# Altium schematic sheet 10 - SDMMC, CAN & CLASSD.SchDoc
size B; CompanyName: Microchip Technology Inc.; Organization: Microchip Technology; Address1: 2355 West Chandler Blvd.; Address2: Chandler, AZ  85224; Address4: USA; DocumentNumber: 10; SheetNumber: 10; SheetTotal: 13; SheetTitle: SDMMC, CAN & CLASSD
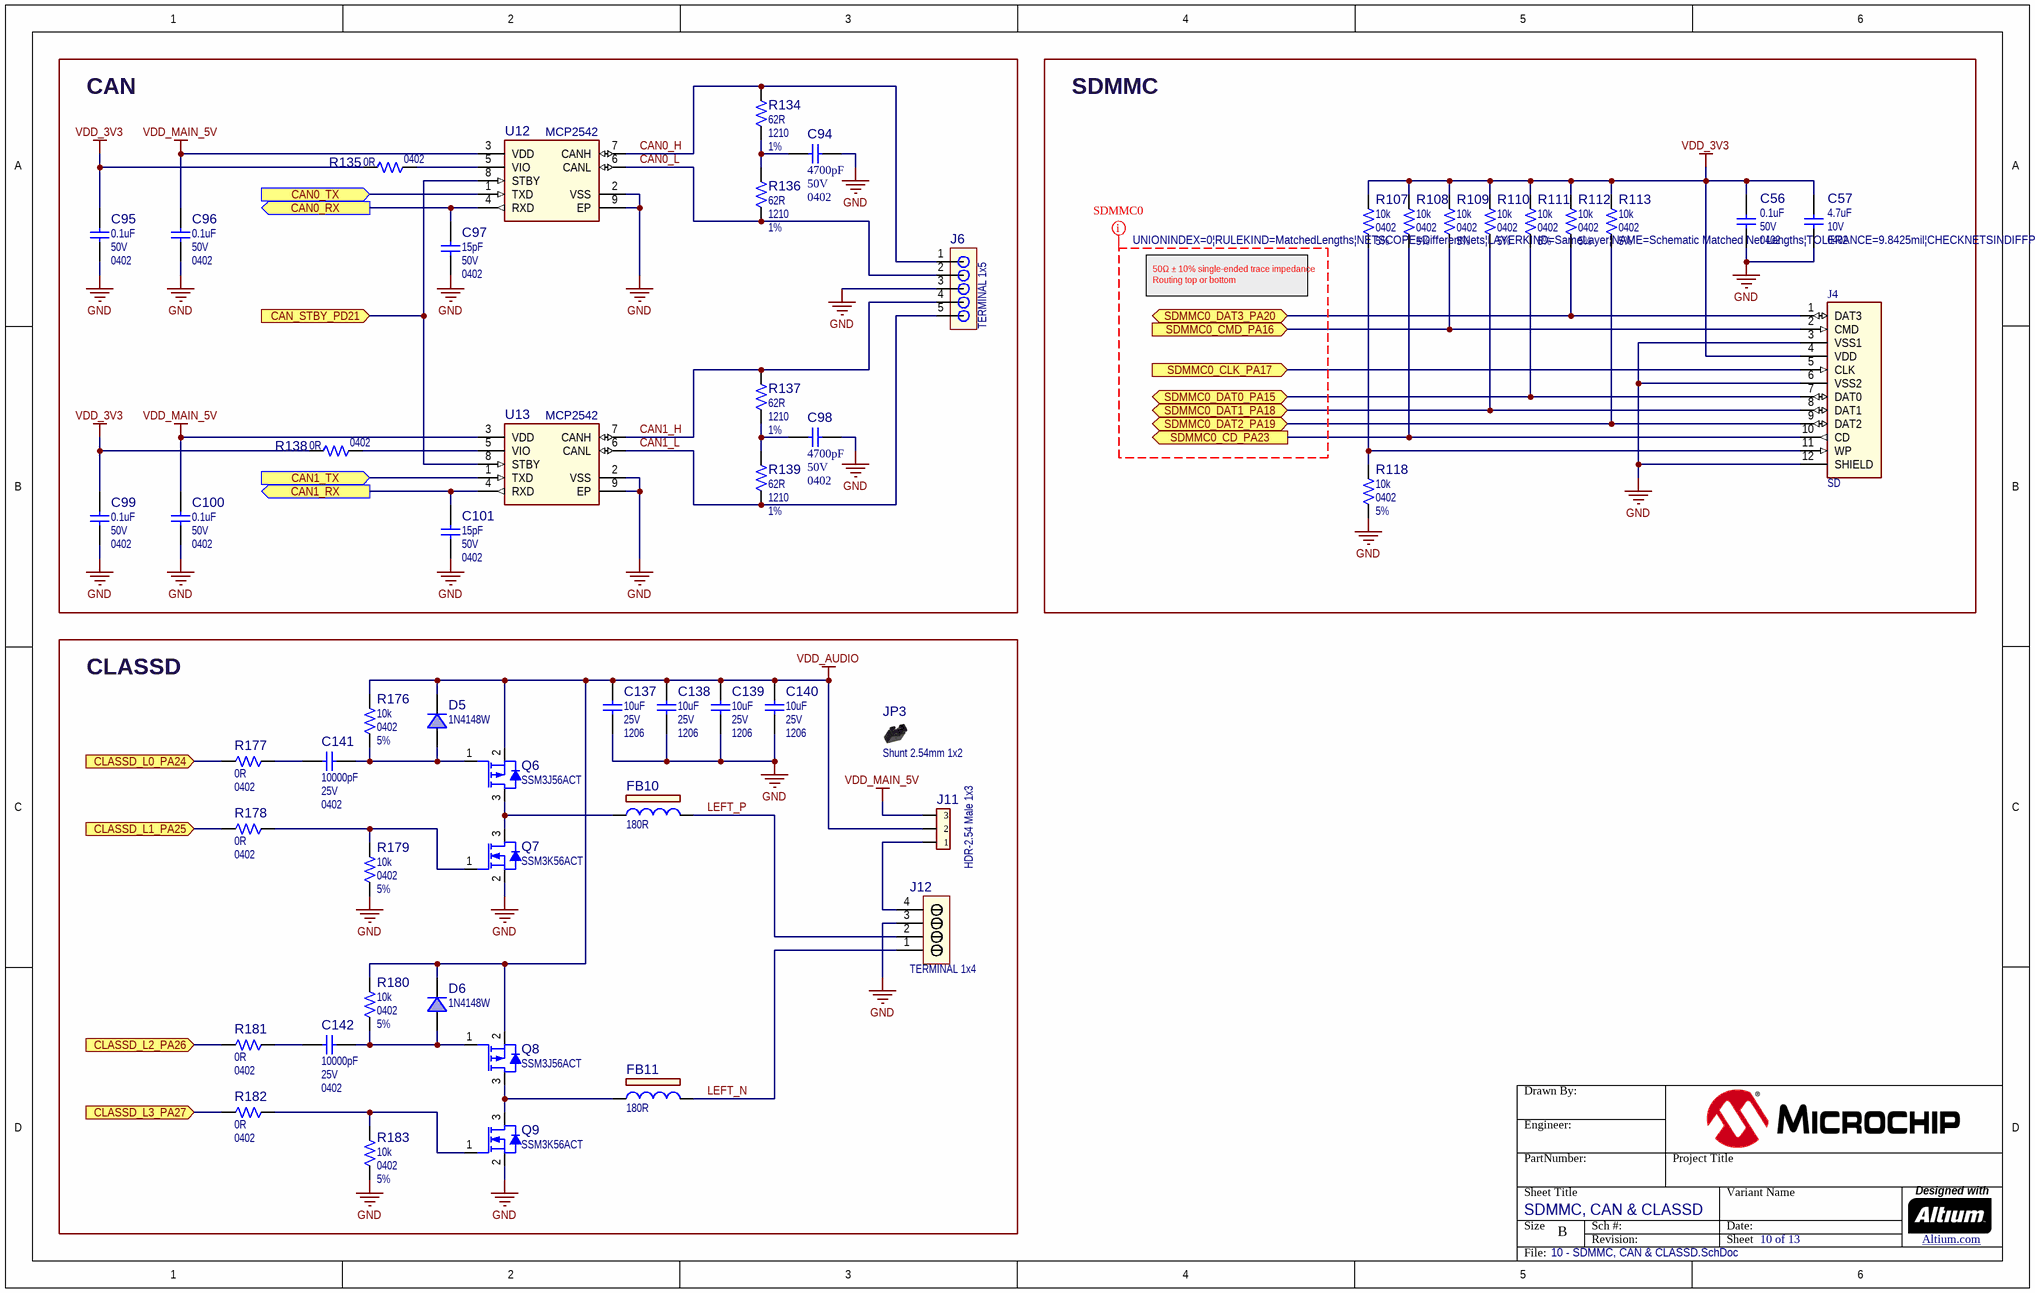
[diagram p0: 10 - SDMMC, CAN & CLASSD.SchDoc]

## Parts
?  (no value)  (graphical)
C56  value 0.1uF  Voltage: 50V  Package: 0402  [CAP_C_0402]  (hidden comment: Capacitor NP)
C57  value 4.7uF  Voltage: 10V  Package: 0402  [CAP_C_0402]  (hidden comment: Capacitor NP)
C94  value 4700pF  Voltage: 50V  Package: 0402  [CAP_C_0402]  (hidden comment: Capacitor NP)
C95  value 0.1uF  Voltage: 50V  Package: 0402  [CAP_C_0402]  (hidden comment: Capacitor NP)
C96  value 0.1uF  Voltage: 50V  Package: 0402  [CAP_C_0402]  (hidden comment: Capacitor NP)
C97  value 15pF  Voltage: 50V  Package: 0402  [CAP_C_0402]  (hidden comment: Capacitor NP)
C98  value 4700pF  Voltage: 50V  Package: 0402  [CAP_C_0402]  (hidden comment: Capacitor NP)
C99  value 0.1uF  Voltage: 50V  Package: 0402  [CAP_C_0402]  (hidden comment: Capacitor NP)
C100  value 0.1uF  Voltage: 50V  Package: 0402  [CAP_C_0402]  (hidden comment: Capacitor NP)
C101  value 15pF  Voltage: 50V  Package: 0402  [CAP_C_0402]  (hidden comment: Capacitor NP)
C137  value 10uF  Voltage: 25V  Package: 1206  [CAP_C_1206]  (hidden comment: Capacitor NP)
C138  value 10uF  Voltage: 25V  Package: 1206  [CAP_C_1206]  (hidden comment: Capacitor NP)
C139  value 10uF  Voltage: 25V  Package: 1206  [CAP_C_1206]  (hidden comment: Capacitor NP)
C140  value 10uF  Voltage: 25V  Package: 1206  [CAP_C_1206]  (hidden comment: Capacitor NP)
C141  value 10000pF  Voltage: 25V  Package: 0402  [CAP_C_0402]  (hidden comment: Capacitor NP)
C142  value 10000pF  Voltage: 25V  Package: 0402  [CAP_C_0402]  (hidden comment: Capacitor NP)
D5  value 1N4148W  [SOD-323]  (hidden comment: Diode Single)
D6  value 1N4148W  [SOD-323]  (hidden comment: Diode Single)
FB10  value 180R  [IND_C_0603]  (hidden comment: Ferrite Bead)
FB11  value 180R  [IND_C_0603]  (hidden comment: Ferrite Bead)
J4  value SD  [10067847-001RLF]  (hidden comment: CON SD CARD 11P_amphenol)
J6  value TERMINAL 1x5  [CON_TERMINAL_3.81_1x5_TH_RA_PHO_1727049]  (hidden comment: CON TERM BLK 1x5 TH Mount)
J11  value HDR-2.54 Male 1x3  [HDR_M_2.54_1x3]  (hidden comment: Header 1x3)
J12  value TERMINAL 1x4  [CON_TERMINAL_2.54_1x4_TH_RA_PHO_1725672]  (hidden comment: Header 1x4)
JP3  value Shunt 2.54mm 1x2  [Jumper_Mechanical]  (hidden comment: Jumper Mechanical)  (mechanical)
Q6  value SSM3J56ACT  [SOT-883]  (hidden comment: Transistor MOS-P GSD)
Q7  value SSM3K56ACT  [SOT-883]  (hidden comment: Transistor MOS-N GSD)
Q8  value SSM3J56ACT  [SOT-883]  (hidden comment: Transistor MOS-P GSD)
Q9  value SSM3K56ACT  [SOT-883]  (hidden comment: Transistor MOS-N GSD)
R107  value 10k  Package: 0402  Tolerance: 5%  [RES_C_0402]  (hidden comment: Resistor)
R108  value 10k  Package: 0402  Tolerance: 5%  [RES_C_0402]  (hidden comment: Resistor)
R109  value 10k  Package: 0402  Tolerance: 5%  [RES_C_0402]  (hidden comment: Resistor)
R110  value 10k  Package: 0402  Tolerance: 5%  [RES_C_0402]  (hidden comment: Resistor)
R111  value 10k  Package: 0402  Tolerance: 5%  [RES_C_0402]  (hidden comment: Resistor)
R112  value 10k  Package: 0402  Tolerance: 5%  [RES_C_0402]  (hidden comment: Resistor)
R113  value 10k  Package: 0402  Tolerance: 5%  [RES_C_0402]  (hidden comment: Resistor)
R118  value 10k  Package: 0402  Tolerance: 5%  [RES_C_0402]  (hidden comment: Resistor)
R134  value 62R  Package: 1210  Tolerance: 1%  [RES_C_1210]  (hidden comment: Resistor)
R135  value 0R  Package: 0402  [RES_C_0402]  (hidden comment: Resistor)
R136  value 62R  Package: 1210  Tolerance: 1%  [RES_C_1210]  (hidden comment: Resistor)
R137  value 62R  Package: 1210  Tolerance: 1%  [RES_C_1210]  (hidden comment: Resistor)
R138  value 0R  Package: 0402  [RES_C_0402]  (hidden comment: Resistor)
R139  value 62R  Package: 1210  Tolerance: 1%  [RES_C_1210]  (hidden comment: Resistor)
R176  value 10k  Package: 0402  Tolerance: 5%  [RES_C_0402]  (hidden comment: Resistor)
R177  value 0R  Package: 0402  [RES_C_0402]  (hidden comment: Resistor)
R178  value 0R  Package: 0402  [RES_C_0402]  (hidden comment: Resistor)
R179  value 10k  Package: 0402  Tolerance: 5%  [RES_C_0402]  (hidden comment: Resistor)
R180  value 10k  Package: 0402  Tolerance: 5%  [RES_C_0402]  (hidden comment: Resistor)
R181  value 0R  Package: 0402  [RES_C_0402]  (hidden comment: Resistor)
R182  value 0R  Package: 0402  [RES_C_0402]  (hidden comment: Resistor)
R183  value 10k  Package: 0402  Tolerance: 5%  [RES_C_0402]  (hidden comment: Resistor)
U12  value MCP2542  [DFN-8_3x3_EP2.4X1.55]  (hidden comment: MCP2542 DFN-8)
U13  value MCP2542  [DFN-8_3x3_EP2.4X1.55]  (hidden comment: MCP2542 DFN-8)

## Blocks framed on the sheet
CAN: C94-C101 J6 R134-R139 U12 U13
SDMMC: C56 C57 J4 R107-R113 R118
CLASSD: C137-C142 D5 D6 FB10 FB11 J11 J12 JP3 Q6-Q9 R176-R183

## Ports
CAN0_RX (out), CAN0_TX (in), CAN1_RX (out), CAN1_TX (in), CAN_STBY_PD21 (in), CLASSD_L0_PA24 (in), CLASSD_L1_PA25 (in), CLASSD_L2_PA26 (in), CLASSD_L3_PA27 (in), SDMMC0_CD_PA23 (out), SDMMC0_CLK_PA17 (in), SDMMC0_CMD_PA16 (in), SDMMC0_DAT0_PA15 (bidir), SDMMC0_DAT1_PA18 (bidir), SDMMC0_DAT2_PA19 (bidir), SDMMC0_DAT3_PA20 (bidir)

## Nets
GND: C56.2 C57.1 C94.1 C95.2 C96.2 C97.1 C98.1 C99.2 C100.2 C101.1 C137.1 C138.1 C139.1 C140.1 J4.3(VSS1) J4.6(VSS2) J4.12(SHIELD) J6.3 J12.3 Q7.2(S) Q9.2(S) R118.1 R179.1 R183.1 U12.2(VSS) U12.9(EP) U13.2(VSS) U13.9(EP)
VDD_3V3: C56.1 C57.2 C95.1 C99.1 J4.4(VDD) R107.2 R108.2 R109.2 R110.2 R111.2 R112.2 R113.2 R135.1 R138.1
VDD_AUDIO: C137.2 C138.2 C139.2 C140.2 D5.2(K) D6.2(K) J11.2 Q6.2(S) Q8.2(S) R176.2 R180.2
VDD_MAIN_5V: C96.1 C100.1 J11.3 U12.3(VDD) U13.3(VDD)
CAN0_H: J6.1 R134.2 U12.7(CANH)
CAN0_L: J6.2 R136.1 U12.6(CANL)
CAN0_RX: C97.2 U12.4(RXD) ; port CAN0_RX
CAN0_TX: U12.1(TXD) ; port CAN0_TX
CAN1_H: J6.4 R137.2 U13.7(CANH)
CAN1_L: J6.5 R139.1 U13.6(CANL)
CAN1_RX: C101.2 U13.4(RXD) ; port CAN1_RX
CAN1_TX: U13.1(TXD) ; port CAN1_TX
CAN_STBY_PD21: U12.8(STBY) U13.8(STBY) ; port CAN_STBY_PD21
CLASSD_L0_PA24: R177.1 ; port CLASSD_L0_PA24
CLASSD_L1_PA25: R178.1 ; port CLASSD_L1_PA25
CLASSD_L2_PA26: R181.1 ; port CLASSD_L2_PA26
CLASSD_L3_PA27: R182.1 ; port CLASSD_L3_PA27
LEFT_N: FB11.2 J12.1
LEFT_P: FB10.2 J12.2
SDMMC0_CD_PA23: J4.10(CD) R108.1 ; port SDMMC0_CD_PA23
SDMMC0_CLK_PA17: J4.5(CLK) ; port SDMMC0_CLK_PA17
SDMMC0_CMD_PA16: J4.2(CMD) R109.1 ; port SDMMC0_CMD_PA16
SDMMC0_DAT0_PA15: J4.7(DAT0) R111.1 ; port SDMMC0_DAT0_PA15
SDMMC0_DAT1_PA18: J4.8(DAT1) R110.1 ; port SDMMC0_DAT1_PA18
SDMMC0_DAT2_PA19: J4.9(DAT2) R113.1 ; port SDMMC0_DAT2_PA19
SDMMC0_DAT3_PA20: J4.1(DAT3) R112.1 ; port SDMMC0_DAT3_PA20
NetC94_2: C94.2 R134.1 R136.2
NetC98_2: C98.2 R137.1 R139.2
NetC141_1: C141.1 R177.2
NetC141_2: C141.2 D5.1(A) Q6.1(G) R176.1
NetC142_1: C142.1 R181.2
NetC142_2: C142.2 D6.1(A) Q8.1(G) R180.1
NetFB10_1: FB10.1 Q6.3(D) Q7.3(D)
NetFB11_1: FB11.1 Q8.3(D) Q9.3(D)
NetJ4_11: J4.11(WP) R107.1 R118.2
NetJ11_1: J11.1 J12.4
NetQ7_1: Q7.1(G) R178.2 R179.2
NetQ9_1: Q9.1(G) R182.2 R183.2
NetR135_2: R135.2 U12.5(VIO)
NetR138_2: R138.2 U13.5(VIO)

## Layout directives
net class SDMMC-0; rule Matched Net Lengths [Tolerance = 0.25mm]: (no net found under the mark)

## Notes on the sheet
- 50Ω ± 10% single-ended trace impedance
  Routing top or bottom

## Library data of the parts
? = Title Block B
C56 = CAP1463: Capacitor; Manufacturer 1: TDK Corporation; Manufacturer Part Number 1: C1005X7R1H104K050BB; Description_: CAP CER 0.1uF 50V 10% X7R SMD 0402; Dev Tools Status: Production; Tolerance: 10%; Temperature Coeffcient: X7R; Type: Ceramic; Populated: YES; Owner: Jamus Griego
C57 = CAP1684: Capacitor; Manufacturer 1: TDK Corporation; Manufacturer Part Number 1: C1005X5R1A475K050BC; Description_: CAP CER 4.7uF 10V 10% X5R SMD 0402; Dev Tools Status: Production; Tolerance: 10%; Temperature Coeffcient: X5R; Type: Ceramic; Owner: Jesus Aviles; Populated: YES
C94 C98 = CAP1391: Capacitor; Manufacturer 1: Murata Electronics North America; Manufacturer Part Number 1: GRM155R71H472KA01D; Description_: CAP CER 4700pF 50V 10% X7R SMD 0402 (Don't Use, Duplicate, use CAP1391); Dev Tools Status: Design; Tolerance: 10%; Temperature Coeffcient: X7R; Type: Ceramic; Owner: Gabor Bihari; Populated: YES
C95 C96 C99 C100 = CAP1463: Capacitor; Manufacturer 1: TDK Corporation; Manufacturer Part Number 1: C1005X7R1H104K050BB; Description_: CAP CER 0.1uF 50V 10% X7R SMD 0402; Dev Tools Status: Production; Tolerance: 10%; Temperature Coeffcient: X7R; Type: Ceramic; Owner: Jamus Griego; Populated: YES
C97 C101 = CAP0608: Capacitor; Manufacturer 1: Murata; Manufacturer Part Number 1: GRM1555C1H150JA01D; Description_: CAP CER 15pF 50V 5% NP0 SMD 0402; Dev Tools Status: Production; Tolerance: 5%; Temperature Coeffcient: NP0; Type: Ceramic; Populated: Yes
C137-C140 = CAP1418: Capacitor; Manufacturer 1: Samsung Electro-Mechanics America, Inc; Manufacturer Part Number 1: CL31B106KAHNFNE; Description_: CAP CER 10uF 25V 10% X7R SMD 1206; Dev Tools Status: Design; Tolerance: 10%; Temperature Coeffcient: X7R; Type: Ceramic; Populated: YES; Owner: Sorin Stanoaia
C141 C142 = CAP0567: Capacitor; Manufacturer 1: TDK; Manufacturer Part Number 1: C1005X7R1E103M; Description_: CAP CER 10000pF 25V 20% X7R SMD 0402; Dev Tools Status: Production; Tolerance: 20%; Temperature Coeffcient: X7R; Type: Ceramic; Populated: YES
D5 D6 = DIODE1102: DIO RECT 1N4148 855mV 300mA 75V SOD-323; Manufacturer 1: Diodes Inc; Manufacturer Part Number 1: 1N4148WS; Description_: DIO RECT 1N4148W 1.25V 150mA 75V SOD-323; Dev Tools Status: Production; Type: Rectifier Single; Forward Current: 150mA; Power: 200mW; Reverse Current: 1uA; Owner: Mihai T(M91442); Populated: Yes
FB10 FB11 = IND1453: FERRITE 180R 1.5A SMD 0603; Manufacturer 1: Murata Electronics North America; Manufacturer Part Number 1: BLM18PG181SN1D; Dev Tools Status: Production; Owner: Dragos Danaila; DCR: 0.09R; Test Frequency: 100MHz; Populated: YES
J4 = CON1752: Manufacturer 1: Amphenol FCI; Description_: 12 (9 + 3) Position Card Connector SD Surface Mount, Right Angle Gold; Dev Tools Status: Design; Owner: Dragos Danaila; Voltage: 17V; Current: 500mA; Populated: YES
J6 = CON1693: Manufacturer 1: Phoenix Contact; Manufacturer Part Number 1: 1727049; Description_: CON TERMINAL 3.81mm 1x5 Female 16-30AWG 13.5A TH R/A; Dev Tools Status: Design; Owner: Ciprian Abramov; Voltage: 300; Current: 13.5A; Populated: YES
J11 = CON0465: Manufacturer 1: Samtec; Manufacturer Part Number 1: TSW-103-07-T-S; Description_: CON HDR-2.54 Male 1x3 Tin 5.84MH TH VERT; Dev Tools Status: Production; Populated: Yes
J12 = CON0005: Manufacturer 1: Phoenix Contact; Manufacturer Part Number 1: 1725672; Description_: CON TERMINAL 2.54mm 1x4 Female 20-30AWG 6A TH R/A; Dev Tools Status: Production; Owner: Sorin Stanoaia; Voltage: 63V; Current: 6A; Populated: YES
JP3 = HW1006: Manufacturer 1: 3M; Manufacturer Part Number 1: 969102-0000-DA; MCHP-ID: HW1006; Description_: MECH HW JUMPER 2.54mm 1x2; Dev Tools Status: Production; Owner: Mike Ragsdale; Populated: MECH
Q6 Q8 = TRA1229: Transistor MOS; Manufacturer 1: Toshiba Semiconductor and Storage; Manufacturer Part Number 1: SSM3J56ACT,L3F; Description_: TRANS FET P-CH SSM3J56ACT 20V 1.4A 0.39R 0.5W SOT-883; Dev Tools Status: Design; Type: FET; Current: 1.4A; Drain to Source Voltage: 20V; Gate to Source Voltage: 8V; Power: 0.5W; Owner: Ciprian Abramov; Populated: YES
Q7 Q9 = TRA1230: Transistor MOS; Manufacturer 1: Toshiba Semiconductor and Storage; Manufacturer Part Number 1: SSM3K56ACT,L3F; Description_: TRANS FET N-CH SSM3K56ACT 20V 1.4A 0.235R 0.5W SOT-883; Dev Tools Status: Design; Type: FET; Current: 1.4A; Drain to Source Voltage: 20V; Gate to Source Voltage: 4.5V; Power: 0.5W; Owner: Ciprian Abramov; Populated: YES
R107 = RSMT0439: Manufacturer 1: Vishay; Manufacturer Part Number 1: CRCW040210K0JNED; Description_: RES TKF 10k 5% 1/16W SMD 0402; Dev Tools Status: Production; Voltage: 50V; Temperature Coeffcient: 100ppm/C; Power: 1/16W; Populated: YES
R108-R113 R176 R179 R180 R183 = RSMT0439: Manufacturer 1: Vishay; Manufacturer Part Number 1: CRCW040210K0JNED; Description_: RES TKF 10k 5% 1/16W SMD 0402; Dev Tools Status: Production; Voltage: 50V; Temperature Coeffcient: 100ppm/C; Power: 1/16W; Populated: Yes
R118 = RSMT0439: Manufacturer 1: Vishay; Manufacturer Part Number 1: CRCW040210K0JNED; Description_: RES TKF 10k 5% 1/16W SMD 0402; Dev Tools Status: Production; Voltage: 50V; Temperature Coeffcient: 100ppm/C; Power: 1/16W; Populated: DNP
R134 R136 R137 R139 = RSMT1222: Manufacturer 1: Yageo; Manufacturer Part Number 1: RC1210FR-0762RL; Description_: RES TKF 62R 1% 1/2W SMD 1210; Dev Tools Status: Production; Voltage: 200V; Temperature Coeffcient: 100PPM/C; Current: 5.56A; Power: 1/2W; Owner: Dragos Danaila; Populated: YES
R135 R138 R177 R178 R181 R182 = RSMT1040: Manufacturer 1: Yageo; Manufacturer Part Number 1: RC0402JR-070RL; Description_: RES TKF 0R 1/16W SMD 0402; Dev Tools Status: Production; Power: 1/16W; Owner: Sompoch Loboonlert; Populated: Yes
U12 U13 = MIC7856: Manufacturer 1: Microchip Technology; Manufacturer Part Number 1: MCP2542FDT-E/MF; Description_: MCHP INTERFACE CAN MCP2542FDT-E/MF DFN-8; MAPS Description: CAN Transceiver; Dev Tools Status: Design; Owner: Ilie Galan; MPC: V7BC6YA7XA00; LeadContent: Pb-FREE; PackingMedia: T/R; Stage: REL; LeadCount: 8; PackageWidth: 3x3x0.9mm; ForceMinOrderQtyMult: True; MinOrderQty: 3300; TempRange: -40C to +125C; tblDeviceFamilyID: 5993; DeviceType: Transceiver; OperatingVoltageMin: 4.5; OperatingVoltageMax: 5.5; StandbyCurrentMax: 15; OperatingCurrentMax: 10; PropDelayMax: 120; ShortCircuit: -58 to +58; TransientVoltage: -150 to +100; ESD: 13; ThermalShutdown: Yes; CMR: +/-12; Masks: 0; Comments: Flexible Data Rate Capable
